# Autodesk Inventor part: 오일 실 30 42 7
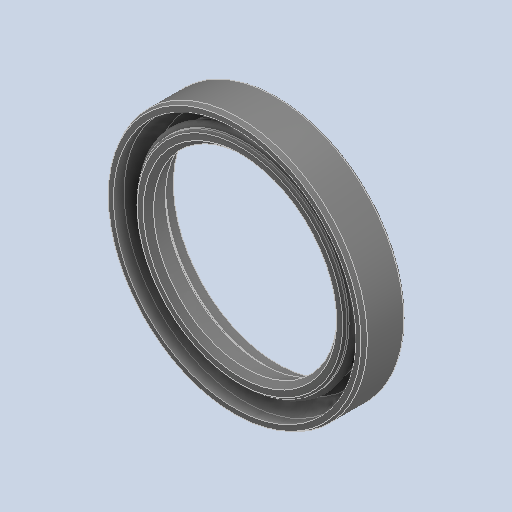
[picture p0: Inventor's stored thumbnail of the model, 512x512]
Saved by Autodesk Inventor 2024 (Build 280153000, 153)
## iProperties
Created: 2025-05
Part Number: 오일 실 30 42 7
Material: 고무
Description: 오일 실 - 스프링 장착, 금속 케이스 SM
Document SubType Name: Modeling
Designer: 11
Density: 0.93 g/cm^3
Appearance: 기본값
Author: jhkim
Sending System: Autodesk Inventor 2026
Preprocessor: ST-DEVELOPER v20.1
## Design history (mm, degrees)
node "오일 실 30 42 71"
node "솔리드1"
body "Solid1"
